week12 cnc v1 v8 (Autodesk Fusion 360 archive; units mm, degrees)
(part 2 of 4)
sketch "Sketch36" plane through (0, 0, 0) normal (0, -1, 0) x axis (1, 0, 0)
  line L1 (349.4349, 118.306) -> (345.9921, 118.306)
  line L2 (353.7135, 82.5845) -> (353.7135, 114.0274)
  line L3 (345.9921, 78.306) -> (349.4349, 78.306)
  line L4 (341.7135, 114.0274) -> (341.7135, 82.5845)
  line L5 (90.3858, 86.9447) -> (100.955, 105.2358)
  line L6 (90.3833, 79.9447) -> (90.3858, 86.9447)
  line L7 (115.751, 79.9356) -> (90.3833, 79.9447)
  line L8 (38.1164, 32.4224) -> (38.0988, 32.4224)
  line L9 (50.6125, 54.0752) -> (38.1164, 32.4224)
  line L10 (50.6113, 61.0752) -> (50.6125, 54.0752)
  line L11 (25.2538, 61.0708) -> (50.6113, 61.0752)
  line L12 (12, 96.0313) -> (12, 127.4742)
  line L13 (0, 91.7528) -> (7.7214, 91.7528)
  line L14 (0, 70.5018) -> (0, 91.7528)
  line L15 (175.6314, 0) -> (70.5018, 0)
  line L16 (452.7135, 50) -> (242.7135, 50)
  line L17 (624.9251, 0) -> (519.7955, 0)
  line L18 (695.4269, 91.7528) -> (695.4269, 70.5018)
  line L19 (687.7056, 91.7528) -> (695.4269, 91.7528)
  line L20 (683.427, 127.4742) -> (683.427, 96.0313)
  line L21 (695.4269, 131.7528) -> (687.7056, 131.7528)
  line L22 (695.4269, 136.7251) -> (695.4269, 131.7528)
  line L23 (695.5, 153.0037) -> (695.5, 141.0744)
  line L24 (655.5, 153.0037) -> (695.5, 153.0037)
  line L25 (655.5, 145.2822) -> (655.5, 153.0037)
  line L26 (606.1357, 141.0037) -> (651.2214, 141.0037)
  line L27 (601.8571, 153.0037) -> (601.8571, 145.2822)
  line L28 (561.8571, 153.0037) -> (601.8571, 153.0037)
  line L29 (561.8571, 145.2822) -> (561.8571, 153.0037)
  line L30 (512.4928, 141.0037) -> (557.5786, 141.0037)
  line L31 (508.2143, 153.0037) -> (508.2143, 145.2822)
  line L32 (468.2143, 153.0037) -> (508.2143, 153.0037)
  line L33 (468.2143, 145.2822) -> (468.2143, 153.0037)
  line L34 (418.85, 141.0037) -> (463.9357, 141.0037)
  line L35 (414.5714, 153.0037) -> (414.5714, 145.2822)
  line L36 (374.5714, 153.0037) -> (414.5714, 153.0037)
  line L37 (374.5714, 145.2822) -> (374.5714, 153.0037)
  line L38 (325.2071, 141.0037) -> (370.2929, 141.0037)
  line L39 (320.9286, 153.0037) -> (320.9286, 145.2822)
  line L40 (280.9286, 153.0037) -> (320.9286, 153.0037)
  line L41 (280.9286, 145.2822) -> (280.9286, 153.0037)
  line L42 (231.5643, 141.0037) -> (276.65, 141.0037)
  line L43 (227.2857, 153.0037) -> (227.2857, 145.2822)
  line L44 (187.2857, 153.0037) -> (227.2857, 153.0037)
  line L45 (187.2857, 145.2822) -> (187.2857, 153.0037)
  line L46 (137.9214, 141.0037) -> (183.0072, 141.0037)
  line L47 (133.6429, 153.0037) -> (133.6429, 145.2822)
  line L48 (93.6429, 153.0037) -> (133.6429, 153.0037)
  line L49 (93.6429, 145.2822) -> (93.6429, 153.0037)
  line L50 (44.2786, 141.0037) -> (89.3643, 141.0037)
  line L51 (40, 153.0037) -> (40, 145.2822)
  line L52 (0, 153.0037) -> (40, 153.0037)
  line L53 (0, 131.7528) -> (0, 153.0037)
  line L54 (7.7214, 131.7528) -> (0, 131.7528)
  line L55 (657.3164, 32.4124) -> (644.8145, 54.0752)
  line L56 (605.0437, 79.9447) -> (579.6759, 79.9356)
  line L57 (605.0412, 86.9447) -> (605.0437, 79.9447)
  line L58 (594.472, 105.2359) -> (605.0412, 86.9447)
  line L59 (644.8157, 61.0752) -> (670.1731, 61.0708)
  line L60 (644.8145, 54.0752) -> (644.8157, 61.0752)
  line L61 (38.1015, 32.3966) -> (38.1164, 32.4224)
  line L62 (38.0673, 32.4337) -> (38.1015, 32.3966)
  line L63 (38.0897, 32.4337) -> (38.0673, 32.4337)
  line L64 (38.1164, 32.4224) -> (38.0897, 32.4337)
  arc A1 centre (343.8528, 116.1667) radius 3.0254 clockwise from (341.7135, 114.0274) to (345.9921, 118.306)
  arc A2 centre (351.5742, 116.1667) radius 3.0254 clockwise from (349.4349, 118.306) to (353.7135, 114.0274)
  arc A3 centre (351.5742, 80.4453) radius 3.0254 clockwise from (353.7135, 82.5845) to (349.4349, 78.306)
  arc A4 centre (343.8528, 80.4453) radius 3.0254 clockwise from (345.9921, 78.306) to (341.7135, 82.5845)
  arc A5 centre (23.3262, 63.4026) radius 3.0254 clockwise from (25.2538, 61.0708) to (20.7983, 65.0647)
  arc A6 centre (70.5018, 70.5018) radius 50 clockwise from (20.7983, 65.0647) to (99.6962, 111.0936)
  arc A7 centre (99.9124, 108.0759) radius 3.0254 clockwise from (99.6962, 111.0936) to (100.955, 105.2358)
  arc A8 centre (117.6767, 77.6022) radius 3.0254 clockwise from (115.751, 79.9356) to (120.2051, 75.9408)
  arc A9 centre (70.5018, 70.5018) radius 50 clockwise from (120.2051, 75.9408) to (38.0988, 32.4224)
  arc A10 centre (9.8607, 129.6135) radius 3.0254 clockwise from (7.7214, 131.7528) to (12, 127.4742)
  arc A11 centre (9.8607, 93.892) radius 3.0254 clockwise from (12, 96.0313) to (7.7214, 91.7528)
  arc A12 centre (70.5018, 70.5018) radius 70.5018 clockwise from (70.5018, 0) to (0, 70.5018)
  arc A13 centre (175.6314, 20) radius 20 clockwise from (194.7977, 14.2857) to (175.6314, 0)
  arc A14 centre (242.7135, 0) radius 50 clockwise from (194.7977, 14.2857) to (242.7135, 50)
  arc A15 centre (452.7135, 0) radius 50 clockwise from (452.7135, 50) to (500.6292, 14.2857)
  arc A16 centre (519.7955, 20) radius 20 clockwise from (519.7955, 0) to (500.6292, 14.2857)
  arc A17 centre (624.9251, 70.5018) radius 70.5018 clockwise from (695.4269, 70.5018) to (624.9251, 0)
  arc A18 centre (685.5663, 93.892) radius 3.0254 clockwise from (687.7056, 91.7528) to (683.427, 96.0313)
  arc A19 centre (685.5663, 129.6135) radius 3.0254 clockwise from (683.427, 127.4742) to (687.7056, 131.7528)
  arc A20 centre (697.5662, 138.8644) radius 3.0254 clockwise from (695.4269, 136.7251) to (695.5, 141.0744)
  arc A21 centre (653.3607, 143.143) radius 3.0254 clockwise from (655.5, 145.2822) to (651.2214, 141.0037)
  arc A22 centre (603.9964, 143.143) radius 3.0254 clockwise from (606.1357, 141.0037) to (601.8571, 145.2822)
  arc A23 centre (559.7179, 143.143) radius 3.0254 clockwise from (561.8571, 145.2822) to (557.5786, 141.0037)
  arc A24 centre (510.3536, 143.143) radius 3.0254 clockwise from (512.4928, 141.0037) to (508.2143, 145.2822)
  arc A25 centre (466.075, 143.143) radius 3.0254 clockwise from (468.2143, 145.2822) to (463.9357, 141.0037)
  arc A26 centre (416.7107, 143.143) radius 3.0254 clockwise from (418.85, 141.0037) to (414.5714, 145.2822)
  arc A27 centre (372.4321, 143.143) radius 3.0254 clockwise from (374.5714, 145.2822) to (370.2929, 141.0037)
  arc A28 centre (323.0679, 143.143) radius 3.0254 clockwise from (325.2071, 141.0037) to (320.9286, 145.2822)
  arc A29 centre (278.7893, 143.143) radius 3.0254 clockwise from (280.9286, 145.2822) to (276.65, 141.0037)
  arc A30 centre (229.425, 143.143) radius 3.0254 clockwise from (231.5643, 141.0037) to (227.2857, 145.2822)
  arc A31 centre (185.1464, 143.143) radius 3.0254 clockwise from (187.2857, 145.2822) to (183.0072, 141.0037)
  arc A32 centre (135.7821, 143.143) radius 3.0254 clockwise from (137.9214, 141.0037) to (133.6429, 145.2822)
  arc A33 centre (91.5036, 143.143) radius 3.0254 clockwise from (93.6429, 145.2822) to (89.3643, 141.0037)
  arc A34 centre (42.1393, 143.143) radius 3.0254 clockwise from (44.2786, 141.0037) to (40, 145.2822)
  arc A35 centre (624.9251, 70.5018) radius 50 clockwise from (657.3164, 32.4124) to (575.2218, 75.9408)
  arc A36 centre (577.7502, 77.6022) radius 3.0254 clockwise from (575.2218, 75.9408) to (579.6759, 79.9356)
  arc A37 centre (595.5146, 108.0759) radius 3.0254 clockwise from (594.472, 105.2359) to (595.7308, 111.0936)
  arc A38 centre (624.9251, 70.5018) radius 50 clockwise from (595.7308, 111.0936) to (674.6286, 65.0647)
  arc A39 centre (672.1007, 63.4026) radius 3.0254 clockwise from (674.6286, 65.0647) to (670.1731, 61.0708)
  point P136 (38.1164, 32.4224)
  point P137 (38.1164, 32.4224)
  point P141 (38.1164, 32.4224)
  coincident P136 P137
  parallel L9 L61
  horizontal L63
  coincident P136 P141
extrude "Extrude5" add sketch "Sketch36" profile of A9 L8 L61 L62 L63 L64 to an object
base_feature "Base Feature31" bodies "Dogbones1 (3)"
combine "Combine1"
base_feature "Base Feature32" bodies "Dogbones1 (4)"
combine "Combine1"
base_feature "Base Feature33" bodies "Dogbones (18)"
combine "Combine2"
base_feature "Base Feature34" bodies "Dogbones1 (5)"
combine "Combine7"
extrude "Extrude2" cut of existing geometry blind -1
extrude "Extrude3" cut of existing geometry blind -3
extrude "Extrude4" cut of existing geometry blind -2
extrude "Extrude5" cut of existing geometry blind -2.5
extrude "Extrude1" cut of existing geometry blind -2
extrude "Extrude2" cut of existing geometry blind -2
extrude "Extrude6" cut of existing geometry blind -2
extrude "Extrude7" cut of existing geometry blind -2
extrude "Extrude8" cut of existing geometry blind -2
extrude "Extrude9" cut of existing geometry blind -2
extrude "Extrude3" cut of existing geometry blind -2
extrude "Extrude4" cut of existing geometry blind -2
extrude "Extrude5" cut of existing geometry blind -2
extrude "Extrude6" cut of existing geometry blind -2
extrude "Extrude7" cut of existing geometry blind -2
extrude "Extrude8" cut of existing geometry blind -2
sketch "Sketch37" plane through (0, 0, 12) normal (0, 0, 1) x axis (-1, 0, 0)
  line L1 (-1675.9921, -108.306) -> (-1679.4349, -108.306)
  line L2 (-1671.7135, -144.0275) -> (-1671.7135, -112.5846)
  line L3 (-1679.4349, -148.306) -> (-1675.9921, -148.306)
  line L4 (-1683.7135, -112.5846) -> (-1683.7135, -144.0275)
  line L5 (-1420.3858, -116.9448) -> (-1430.955, -135.2359)
  line L6 (-1420.3833, -109.9448) -> (-1420.3858, -116.9448)
  line L7 (-1445.751, -109.9357) -> (-1420.3833, -109.9448)
  line L8 (-1368.1164, -62.4225) -> (-1368.0988, -62.4225)
  line L9 (-1380.6125, -84.0753) -> (-1370.7136, -66.9229)
  line L10 (-1380.6113, -91.0753) -> (-1380.6125, -84.0753)
  line L11 (-1355.2538, -91.0708) -> (-1380.6113, -91.0753)
  line L12 (-1935.0437, -109.9448) -> (-1909.6759, -109.9357)
  line L13 (-1935.0412, -116.9448) -> (-1935.0437, -109.9448)
  line L14 (-1922.5334, -138.5909) -> (-1935.0412, -116.9448)
  line L15 (-1907.7027, -116.9349) -> (-1907.7028, -116.9349)
  line L16 (-1974.8157, -91.0753) -> (-2000.1731, -91.0708)
  line L17 (-1974.8145, -84.0753) -> (-1974.8157, -91.0753)
  line L18 (-1987.3106, -62.4225) -> (-1974.8145, -84.0753)
  line L19 (-1987.3281, -62.4225) -> (-1987.3106, -62.4225)
  line L20 (-1330, -121.7528) -> (-1337.7214, -121.7528)
  line L21 (-1330, -100.5019) -> (-1330, -121.7528)
  line L22 (-1505.6314, -30.0001) -> (-1400.5018, -30.0001)
  line L23 (-1782.7135, -80.0001) -> (-1572.7135, -80.0001)
  line L24 (-1954.9251, -30.0001) -> (-1849.7955, -30.0001)
  line L25 (-2025.4269, -121.7528) -> (-2025.4269, -100.5019)
  line L26 (-2017.7056, -121.7528) -> (-2025.4269, -121.7528)
  line L27 (-2013.427, -157.4743) -> (-2013.427, -126.0314)
  line L28 (-2025.4269, -161.7528) -> (-2017.7056, -161.7528)
  line L29 (-2025.4269, -171.0037) -> (-2025.4269, -161.7528)
  line L30 (-2025.5, -171.0037) -> (-2025.4269, -171.0037)
  line L31 (-2025.5, -183.0037) -> (-2025.5, -171.0037)
  line L32 (-1985.5, -183.0037) -> (-2025.5, -183.0037)
  line L33 (-1985.5, -175.2823) -> (-1985.5, -183.0037)
  line L34 (-1936.1357, -171.0037) -> (-1981.2214, -171.0037)
  line L35 (-1931.8571, -183.0037) -> (-1931.8571, -175.2823)
  line L36 (-1891.8571, -183.0037) -> (-1931.8571, -183.0037)
  line L37 (-1891.8571, -175.2823) -> (-1891.8571, -183.0037)
  line L38 (-1842.4928, -171.0037) -> (-1887.5786, -171.0037)
  line L39 (-1838.2143, -183.0037) -> (-1838.2143, -175.2823)
  line L40 (-1798.2143, -183.0037) -> (-1838.2143, -183.0037)
  line L41 (-1798.2143, -175.2823) -> (-1798.2143, -183.0037)
  line L42 (-1748.85, -171.0037) -> (-1793.9357, -171.0037)
  line L43 (-1744.5714, -183.0037) -> (-1744.5714, -175.2823)
  line L44 (-1704.5714, -183.0037) -> (-1744.5714, -183.0037)
  line L45 (-1704.5714, -175.2823) -> (-1704.5714, -183.0037)
  line L46 (-1655.2071, -171.0037) -> (-1700.2929, -171.0037)
  line L47 (-1650.9286, -183.0037) -> (-1650.9286, -175.2823)
  line L48 (-1610.9286, -183.0037) -> (-1650.9286, -183.0037)
  line L49 (-1610.9286, -175.2823) -> (-1610.9286, -183.0037)
  line L50 (-1561.5643, -171.0037) -> (-1606.65, -171.0037)
  line L51 (-1557.2857, -183.0037) -> (-1557.2857, -175.2823)
  line L52 (-1517.2857, -183.0037) -> (-1557.2857, -183.0037)
  line L53 (-1517.2857, -175.2823) -> (-1517.2857, -183.0037)
  line L54 (-1467.9214, -171.0037) -> (-1513.0072, -171.0037)
  line L55 (-1463.6429, -183.0037) -> (-1463.6429, -175.2823)
  line L56 (-1423.6429, -183.0037) -> (-1463.6429, -183.0037)
  line L57 (-1423.6429, -175.2823) -> (-1423.6429, -183.0037)
  line L58 (-1374.2786, -171.0037) -> (-1419.3643, -171.0037)
  line L59 (-1370, -183.0037) -> (-1370, -175.2823)
  line L60 (-1330, -183.0037) -> (-1370, -183.0037)
  line L61 (-1330, -161.7528) -> (-1330, -183.0037)
  line L62 (-1337.7214, -161.7528) -> (-1330, -161.7528)
  line L63 (-1342, -126.0314) -> (-1342, -157.4743)
  line L64 (-1922.5334, -138.5909) -> (-1935.0412, -116.9448)
  line L65 (-1906.94, -143.0545) -> (-1922.5334, -138.5909)
  line L66 (-1903.6641, -113.9992) -> (-1906.94, -143.0545)
  line L67 (-1912.281, -115.4947) -> (-1903.6641, -113.9992)
  line L68 (-1922.5334, -138.5909) -> (-1912.281, -115.4947)
  arc A1 centre (-1681.5742, -110.4453) radius 3.0254 clockwise from (-1683.7135, -112.5846) to (-1679.4349, -108.306)
  arc A2 centre (-1673.8528, -110.4453) radius 3.0254 clockwise from (-1675.9921, -108.306) to (-1671.7135, -112.5846)
  arc A3 centre (-1673.8528, -146.1668) radius 3.0254 clockwise from (-1671.7135, -144.0275) to (-1675.9921, -148.306)
  arc A4 centre (-1681.5742, -146.1668) radius 3.0254 clockwise from (-1679.4349, -148.306) to (-1683.7135, -144.0275)
  arc A5 centre (-1353.3262, -93.4026) radius 3.0254 clockwise from (-1355.2538, -91.0708) to (-1350.7983, -95.0648)
  arc A6 centre (-1400.5018, -100.5019) radius 50 clockwise from (-1350.7983, -95.0648) to (-1429.6962, -141.0936)
  arc A7 centre (-1429.9124, -138.076) radius 3.0254 clockwise from (-1429.6962, -141.0936) to (-1430.955, -135.2359)
  arc A8 centre (-1447.6767, -107.6023) radius 3.0254 clockwise from (-1445.751, -109.9357) to (-1450.2051, -105.9409)
  arc A9 centre (-1400.5018, -100.5019) radius 50 clockwise from (-1450.2051, -105.9409) to (-1369.7384, -61.0861)
  arc A10 centre (-1370.7142, -63.9229) radius 3 clockwise from (-1369.7384, -61.0861) to (-1368.1337, -62.3928)
  arc A11 centre (-1400.5018, -100.5019) radius 50 clockwise from (-1368.1337, -62.3928) to (-1368.0988, -62.4225)
  arc A12 centre (-1370.7142, -63.9229) radius 3 clockwise from (-1368.1164, -62.4225) to (-1370.7136, -66.9229)
  arc A13 centre (-1907.7502, -107.6023) radius 3.0254 clockwise from (-1905.2218, -105.9409) to (-1909.6759, -109.9357)
  arc A14 centre (-1954.9252, -100.5019) radius 50 clockwise from (-1907.7028, -116.9349) to (-1922.5334, -138.5909)
  arc A15 centre (-1954.9251, -100.5019) radius 50 clockwise from (-1907.7027, -116.9349) to (-2004.6286, -95.0648)
  arc A16 centre (-2002.1007, -93.4026) radius 3.0254 clockwise from (-2004.6286, -95.0648) to (-2000.1731, -91.0708)
  arc A17 centre (-1954.9251, -100.5019) radius 50 clockwise from (-1987.3281, -62.4225) to (-1905.2218, -105.9409)
  arc A18 centre (-1339.8607, -123.8921) radius 3.0254 clockwise from (-1342, -126.0314) to (-1337.7214, -121.7528)
  arc A19 centre (-1400.5018, -100.5019) radius 70.5018 clockwise from (-1400.5018, -30.0001) to (-1330, -100.5019)
  arc A20 centre (-1505.6314, -50.0001) radius 20 clockwise from (-1524.7977, -44.2858) to (-1505.6314, -30.0001)
  arc A21 centre (-1572.7135, -30.0001) radius 50 clockwise from (-1524.7977, -44.2858) to (-1572.7135, -80.0001)
  arc A22 centre (-1782.7135, -30.0001) radius 50 clockwise from (-1782.7135, -80.0001) to (-1830.6292, -44.2858)
  arc A23 centre (-1849.7955, -50.0001) radius 20 clockwise from (-1849.7955, -30.0001) to (-1830.6292, -44.2858)
  arc A24 centre (-1954.9251, -100.5019) radius 70.5018 clockwise from (-2025.4269, -100.5019) to (-1954.9251, -30.0001)
  arc A25 centre (-2015.5663, -123.8921) radius 3.0254 clockwise from (-2017.7056, -121.7528) to (-2013.427, -126.0314)
  arc A26 centre (-2015.5663, -159.6135) radius 3.0254 clockwise from (-2013.427, -157.4743) to (-2017.7056, -161.7528)
  arc A27 centre (-1983.3607, -173.143) radius 3.0254 clockwise from (-1985.5, -175.2823) to (-1981.2214, -171.0037)
  arc A28 centre (-1933.9964, -173.143) radius 3.0254 clockwise from (-1936.1357, -171.0037) to (-1931.8571, -175.2823)
  arc A29 centre (-1889.7179, -173.143) radius 3.0254 clockwise from (-1891.8571, -175.2823) to (-1887.5786, -171.0037)
  arc A30 centre (-1840.3536, -173.143) radius 3.0254 clockwise from (-1842.4928, -171.0037) to (-1838.2143, -175.2823)
  arc A31 centre (-1796.075, -173.143) radius 3.0254 clockwise from (-1798.2143, -175.2823) to (-1793.9357, -171.0037)
  arc A32 centre (-1746.7107, -173.143) radius 3.0254 clockwise from (-1748.85, -171.0037) to (-1744.5714, -175.2823)
  arc A33 centre (-1702.4321, -173.143) radius 3.0254 clockwise from (-1704.5714, -175.2823) to (-1700.2929, -171.0037)
  arc A34 centre (-1653.0679, -173.143) radius 3.0254 clockwise from (-1655.2071, -171.0037) to (-1650.9286, -175.2823)
  arc A35 centre (-1608.7893, -173.143) radius 3.0254 clockwise from (-1610.9286, -175.2823) to (-1606.65, -171.0037)
  arc A36 centre (-1559.425, -173.143) radius 3.0254 clockwise from (-1561.5643, -171.0037) to (-1557.2857, -175.2823)
  arc A37 centre (-1515.1464, -173.143) radius 3.0254 clockwise from (-1517.2857, -175.2823) to (-1513.0072, -171.0037)
  arc A38 centre (-1465.7821, -173.143) radius 3.0254 clockwise from (-1467.9214, -171.0037) to (-1463.6429, -175.2823)
  arc A39 centre (-1421.5036, -173.143) radius 3.0254 clockwise from (-1423.6429, -175.2823) to (-1419.3643, -171.0037)
  arc A40 centre (-1372.1393, -173.143) radius 3.0254 clockwise from (-1374.2786, -171.0037) to (-1370, -175.2823)
  arc A41 centre (-1339.8607, -159.6135) radius 3.0254 clockwise from (-1337.7214, -161.7528) to (-1342, -157.4743)
  point P142 (-1922.5334, -138.5909)
  point P143 (-1922.5334, -138.5909)
  point P147 (-1922.5334, -138.5909)
  coincident P142 P143
  coincident P142 P147
extrude "Extrude1" add sketch "Sketch37" profile of A14 L15 A15 L65 to an object
base_feature "Base Feature35" bodies "Dogbones1 (6)"
combine "Combine7"
sketch "Sketch38" plane through (0, 0, 12) normal (0, 0, 1) x axis (-1, 0, 0)
  line L1 (-1935.0437, -109.9448) -> (-1909.6759, -109.9357)
  line L2 (-1935.0412, -116.9448) -> (-1935.0437, -109.9448)
  line L3 (-1922.5334, -138.5909) -> (-1935.0412, -116.9448)
  line L4 (-1922.5333, -138.5909) -> (-1922.5334, -138.5909)
  line L5 (-1974.8157, -91.0753) -> (-2000.1731, -91.0708)
  line L6 (-1974.8145, -84.0753) -> (-1974.8157, -91.0753)
  line L7 (-1987.3106, -62.4225) -> (-1974.8145, -84.0753)
  line L8 (-1987.3281, -62.4225) -> (-1987.3106, -62.4225)
  line L9 (-1420.3858, -116.9448) -> (-1430.955, -135.2359)
  line L10 (-1420.3833, -109.9448) -> (-1420.3858, -116.9448)
  line L11 (-1445.751, -109.9357) -> (-1420.3833, -109.9448)
  line L12 (-1368.1164, -62.4225) -> (-1368.0988, -62.4225)
  line L13 (-1380.6125, -84.0753) -> (-1370.7136, -66.9229)
  line L14 (-1380.6113, -91.0753) -> (-1380.6125, -84.0753)
  line L15 (-1355.2538, -91.0708) -> (-1380.6113, -91.0753)
  line L16 (-1675.9921, -108.306) -> (-1679.4349, -108.306)
  line L17 (-1671.7135, -144.0275) -> (-1671.7135, -112.5846)
  line L18 (-1679.4349, -148.306) -> (-1675.9921, -148.306)
  line L19 (-1683.7135, -112.5846) -> (-1683.7135, -144.0275)
  line L20 (-2025.5, -183.0037) -> (-2025.5, -171.0744)
  line L21 (-1985.5, -183.0037) -> (-2025.5, -183.0037)
  line L22 (-1985.5, -175.2823) -> (-1985.5, -183.0037)
  line L23 (-1936.1357, -171.0037) -> (-1981.2214, -171.0037)
  line L24 (-1931.8571, -183.0037) -> (-1931.8571, -175.2823)
  line L25 (-1891.8571, -183.0037) -> (-1931.8571, -183.0037)
  line L26 (-1891.8571, -175.2823) -> (-1891.8571, -183.0037)
  line L27 (-1842.4928, -171.0037) -> (-1887.5786, -171.0037)
  line L28 (-1838.2143, -183.0037) -> (-1838.2143, -175.2823)
  line L29 (-1798.2143, -183.0037) -> (-1838.2143, -183.0037)
  line L30 (-1798.2143, -175.2823) -> (-1798.2143, -183.0037)
  line L31 (-1748.85, -171.0037) -> (-1793.9357, -171.0037)
  line L32 (-1744.5714, -183.0037) -> (-1744.5714, -175.2823)
  line L33 (-1704.5714, -183.0037) -> (-1744.5714, -183.0037)
  line L34 (-1704.5714, -175.2823) -> (-1704.5714, -183.0037)
  line L35 (-1655.2071, -171.0037) -> (-1700.2929, -171.0037)
  line L36 (-1650.9286, -183.0037) -> (-1650.9286, -175.2823)
  line L37 (-1610.9286, -183.0037) -> (-1650.9286, -183.0037)
  line L38 (-1610.9286, -175.2823) -> (-1610.9286, -183.0037)
  line L39 (-1561.5643, -171.0037) -> (-1606.65, -171.0037)
  line L40 (-1557.2857, -183.0037) -> (-1557.2857, -175.2823)
  line L41 (-1517.2857, -183.0037) -> (-1557.2857, -183.0037)
  line L42 (-1517.2857, -175.2823) -> (-1517.2857, -183.0037)
  line L43 (-1467.9214, -171.0037) -> (-1513.0072, -171.0037)
  line L44 (-1463.6429, -183.0037) -> (-1463.6429, -175.2823)
  line L45 (-1423.6429, -183.0037) -> (-1463.6429, -183.0037)
  line L46 (-1423.6429, -175.2823) -> (-1423.6429, -183.0037)
  line L47 (-1374.2786, -171.0037) -> (-1419.3643, -171.0037)
  line L48 (-1370, -183.0037) -> (-1370, -175.2823)
  line L49 (-1330, -183.0037) -> (-1370, -183.0037)
  line L50 (-1330, -161.7528) -> (-1330, -183.0037)
  line L51 (-1337.7214, -161.7528) -> (-1330, -161.7528)
  line L52 (-1342, -126.0314) -> (-1342, -157.4743)
  line L53 (-1330, -121.7528) -> (-1337.7214, -121.7528)
  line L54 (-1330, -100.5019) -> (-1330, -121.7528)
  line L55 (-1505.6314, -30.0001) -> (-1400.5018, -30.0001)
  line L56 (-1782.7135, -80.0001) -> (-1572.7135, -80.0001)
  line L57 (-1954.9251, -30.0001) -> (-1849.7955, -30.0001)
  line L58 (-2025.4269, -121.7528) -> (-2025.4269, -100.5019)
  line L59 (-2017.7056, -121.7528) -> (-2025.4269, -121.7528)
  line L60 (-2013.427, -157.4743) -> (-2013.427, -126.0314)
  line L61 (-2025.4269, -161.7528) -> (-2017.7056, -161.7528)
  line L62 (-2025.4269, -166.7252) -> (-2025.4269, -161.7528)
  line L63 (-1987.3281, -62.4225) -> (-1987.3106, -62.4225)
  line L64 (-1987.3227, -62.4017) -> (-1987.3106, -62.4225)
  line L65 (-1987.3382, -62.4335) -> (-1987.3227, -62.4017)
  line L66 (-1987.3287, -62.4382) -> (-1987.3382, -62.4335)
  line L67 (-1987.3106, -62.4225) -> (-1987.3287, -62.4382)
  arc A1 centre (-1907.7502, -107.6023) radius 3.0254 clockwise from (-1905.2218, -105.9409) to (-1909.6759, -109.9357)
  arc A2 centre (-1954.9251, -100.5019) radius 50 clockwise from (-1922.5333, -138.5909) to (-2004.6286, -95.0648)
  arc A3 centre (-2002.1007, -93.4026) radius 3.0254 clockwise from (-2004.6286, -95.0648) to (-2000.1731, -91.0708)
  arc A4 centre (-1954.9251, -100.5019) radius 50 clockwise from (-1987.3281, -62.4225) to (-1905.2218, -105.9409)
  arc A5 centre (-1353.3262, -93.4026) radius 3.0254 clockwise from (-1355.2538, -91.0708) to (-1350.7983, -95.0648)
  arc A6 centre (-1400.5018, -100.5019) radius 50 clockwise from (-1350.7983, -95.0648) to (-1429.6962, -141.0936)
  arc A7 centre (-1429.9124, -138.076) radius 3.0254 clockwise from (-1429.6962, -141.0936) to (-1430.955, -135.2359)
  arc A8 centre (-1447.6767, -107.6023) radius 3.0254 clockwise from (-1445.751, -109.9357) to (-1450.2051, -105.9409)
  arc A9 centre (-1400.5018, -100.5019) radius 50 clockwise from (-1450.2051, -105.9409) to (-1369.7384, -61.0861)
  arc A10 centre (-1370.7142, -63.9229) radius 3 clockwise from (-1369.7384, -61.0861) to (-1368.1337, -62.3928)
  arc A11 centre (-1400.5018, -100.5019) radius 50 clockwise from (-1368.1337, -62.3928) to (-1368.0988, -62.4225)
  arc A12 centre (-1370.7142, -63.9229) radius 3 clockwise from (-1368.1164, -62.4225) to (-1370.7136, -66.9229)
  arc A13 centre (-1681.5742, -110.4453) radius 3.0254 clockwise from (-1683.7135, -112.5846) to (-1679.4349, -108.306)
  arc A14 centre (-1673.8528, -110.4453) radius 3.0254 clockwise from (-1675.9921, -108.306) to (-1671.7135, -112.5846)
  arc A15 centre (-1673.8528, -146.1668) radius 3.0254 clockwise from (-1671.7135, -144.0275) to (-1675.9921, -148.306)
  arc A16 centre (-1681.5742, -146.1668) radius 3.0254 clockwise from (-1679.4349, -148.306) to (-1683.7135, -144.0275)
  arc A17 centre (-2027.5662, -168.8645) radius 3.0254 clockwise from (-2025.4269, -166.7252) to (-2025.5, -171.0744)
  arc A18 centre (-1983.3607, -173.143) radius 3.0254 clockwise from (-1985.5, -175.2823) to (-1981.2214, -171.0037)
  arc A19 centre (-1933.9964, -173.143) radius 3.0254 clockwise from (-1936.1357, -171.0037) to (-1931.8571, -175.2823)
  arc A20 centre (-1889.7179, -173.143) radius 3.0254 clockwise from (-1891.8571, -175.2823) to (-1887.5786, -171.0037)
  arc A21 centre (-1840.3536, -173.143) radius 3.0254 clockwise from (-1842.4928, -171.0037) to (-1838.2143, -175.2823)
  arc A22 centre (-1796.075, -173.143) radius 3.0254 clockwise from (-1798.2143, -175.2823) to (-1793.9357, -171.0037)
  arc A23 centre (-1746.7107, -173.143) radius 3.0254 clockwise from (-1748.85, -171.0037) to (-1744.5714, -175.2823)
  arc A24 centre (-1702.4321, -173.143) radius 3.0254 clockwise from (-1704.5714, -175.2823) to (-1700.2929, -171.0037)
  arc A25 centre (-1653.0679, -173.143) radius 3.0254 clockwise from (-1655.2071, -171.0037) to (-1650.9286, -175.2823)
  arc A26 centre (-1608.7893, -173.143) radius 3.0254 clockwise from (-1610.9286, -175.2823) to (-1606.65, -171.0037)
  arc A27 centre (-1559.425, -173.143) radius 3.0254 clockwise from (-1561.5643, -171.0037) to (-1557.2857, -175.2823)
  arc A28 centre (-1515.1464, -173.143) radius 3.0254 clockwise from (-1517.2857, -175.2823) to (-1513.0072, -171.0037)
  arc A29 centre (-1465.7821, -173.143) radius 3.0254 clockwise from (-1467.9214, -171.0037) to (-1463.6429, -175.2823)
  arc A30 centre (-1421.5036, -173.143) radius 3.0254 clockwise from (-1423.6429, -175.2823) to (-1419.3643, -171.0037)
  arc A31 centre (-1372.1393, -173.143) radius 3.0254 clockwise from (-1374.2786, -171.0037) to (-1370, -175.2823)
  arc A32 centre (-1339.8607, -159.6135) radius 3.0254 clockwise from (-1337.7214, -161.7528) to (-1342, -157.4743)
  arc A33 centre (-1339.8607, -123.8921) radius 3.0254 clockwise from (-1342, -126.0314) to (-1337.7214, -121.7528)
  arc A34 centre (-1400.5018, -100.5019) radius 70.5018 clockwise from (-1400.5018, -30.0001) to (-1330, -100.5019)
  arc A35 centre (-1505.6314, -50.0001) radius 20 clockwise from (-1524.7977, -44.2858) to (-1505.6314, -30.0001)
  arc A36 centre (-1572.7135, -30.0001) radius 50 clockwise from (-1524.7977, -44.2858) to (-1572.7135, -80.0001)
  arc A37 centre (-1782.7135, -30.0001) radius 50 clockwise from (-1782.7135, -80.0001) to (-1830.6292, -44.2858)
  arc A38 centre (-1849.7955, -50.0001) radius 20 clockwise from (-1849.7955, -30.0001) to (-1830.6292, -44.2858)
  arc A39 centre (-1954.9251, -100.5019) radius 70.5018 clockwise from (-2025.4269, -100.5019) to (-1954.9251, -30.0001)
  arc A40 centre (-2015.5663, -123.8921) radius 3.0254 clockwise from (-2017.7056, -121.7528) to (-2013.427, -126.0314)
  arc A41 centre (-2015.5663, -159.6135) radius 3.0254 clockwise from (-2013.427, -157.4743) to (-2017.7056, -161.7528)
  point P140 (-1987.3106, -62.4225)
  point P142 (-1987.3106, -62.4225)
  coincident P140 P142
  perpendicular L65 L66
  parallel L7 L64
extrude "Extrude2" add sketch "Sketch38" profile of L8 A4 L63 L64 L65 L66 L67 to an object
base_feature "Base Feature36" bodies "Dogbones (19)"
combine "Combine8"
sketch "Sketch40" plane through (0, 0, 0) normal (0, 0, -1) x axis (1, 0, 0)
  line L1 (1683.7135, -144.0275) -> (1683.7135, -112.5846)
  line L2 (1675.9921, -148.306) -> (1679.4349, -148.306)
  line L3 (1671.7135, -112.5846) -> (1671.7135, -144.0275)
  line L4 (1679.4349, -108.306) -> (1675.9921, -108.306)
  line L5 (1380.6113, -91.0753) -> (1355.2538, -91.0708)
  line L6 (1380.6125, -84.0753) -> (1380.6113, -91.0753)
  line L7 (1370.7136, -66.9229) -> (1380.6125, -84.0753)
  line L8 (1368.0988, -62.4225) -> (1368.1164, -62.4225)
  line L9 (1420.3833, -109.9448) -> (1445.751, -109.9357)
  line L10 (1420.3858, -116.9448) -> (1420.3833, -109.9448)
  line L11 (1430.955, -135.2359) -> (1420.3858, -116.9448)
  line L12 (2025.4269, -161.7528) -> (2025.4269, -166.7252)
  line L13 (2017.7056, -161.7528) -> (2025.4269, -161.7528)
  line L14 (2013.427, -126.0314) -> (2013.427, -157.4743)
  line L15 (2025.4269, -121.7528) -> (2017.7056, -121.7528)
  line L16 (2025.4269, -100.5019) -> (2025.4269, -121.7528)
  line L17 (1849.7955, -30.0001) -> (1954.9251, -30.0001)
  line L18 (1572.7135, -80.0001) -> (1782.7135, -80.0001)
  line L19 (1400.5018, -30.0001) -> (1505.6314, -30.0001)
  line L20 (1330, -121.7528) -> (1330, -100.5019)
  line L21 (1337.7214, -121.7528) -> (1330, -121.7528)
  line L22 (1342, -157.4743) -> (1342, -126.0314)
  line L23 (1330, -161.7528) -> (1337.7214, -161.7528)
  line L24 (1330, -183.0037) -> (1330, -161.7528)
  line L25 (1370, -183.0037) -> (1330, -183.0037)
  line L26 (1370, -175.2823) -> (1370, -183.0037)
  line L27 (1419.3643, -171.0037) -> (1374.2786, -171.0037)
  line L28 (1423.6429, -183.0037) -> (1423.6429, -175.2823)
  line L29 (1463.6429, -183.0037) -> (1423.6429, -183.0037)
  line L30 (1463.6429, -175.2823) -> (1463.6429, -183.0037)
  line L31 (1513.0072, -171.0037) -> (1467.9214, -171.0037)
  line L32 (1517.2857, -183.0037) -> (1517.2857, -175.2823)
  line L33 (1557.2857, -183.0037) -> (1517.2857, -183.0037)
  line L34 (1557.2857, -175.2823) -> (1557.2857, -183.0037)
  line L35 (1606.65, -171.0037) -> (1561.5643, -171.0037)
  line L36 (1610.9286, -183.0037) -> (1610.9286, -175.2823)
  line L37 (1650.9286, -183.0037) -> (1610.9286, -183.0037)
  line L38 (1650.9286, -175.2823) -> (1650.9286, -183.0037)
  line L39 (1700.2929, -171.0037) -> (1655.2071, -171.0037)
  line L40 (1704.5714, -183.0037) -> (1704.5714, -175.2823)
  line L41 (1744.5714, -183.0037) -> (1704.5714, -183.0037)
  line L42 (1744.5714, -175.2823) -> (1744.5714, -183.0037)
  line L43 (1793.9357, -171.0037) -> (1748.85, -171.0037)
  line L44 (1798.2143, -183.0037) -> (1798.2143, -175.2823)
  line L45 (1838.2143, -183.0037) -> (1798.2143, -183.0037)
  line L46 (1838.2143, -175.2823) -> (1838.2143, -183.0037)
  line L47 (1887.5786, -171.0037) -> (1842.4928, -171.0037)
  line L48 (1891.8571, -183.0037) -> (1891.8571, -175.2823)
  line L49 (1931.8571, -183.0037) -> (1891.8571, -183.0037)
  line L50 (1931.8571, -175.2823) -> (1931.8571, -183.0037)
  line L51 (1981.2214, -171.0037) -> (1936.1357, -171.0037)
  line L52 (1985.5, -183.0037) -> (1985.5, -175.2823)
  line L53 (2025.5, -183.0037) -> (1985.5, -183.0037)
  line L54 (2025.5, -171.0744) -> (2025.5, -183.0037)
  line L55 (1974.8145, -84.0753) -> (1985.3802, -65.7675)
  line L56 (1974.8157, -91.0753) -> (1974.8145, -84.0753)
  line L57 (2000.1731, -91.0708) -> (1974.8157, -91.0753)
  line L58 (1922.5334, -138.5909) -> (1922.5333, -138.5909)
  line L59 (1935.0412, -116.9448) -> (1922.5334, -138.5909)
  line L60 (1935.0437, -109.9448) -> (1935.0412, -116.9448)
  line L61 (1909.6759, -109.9357) -> (1935.0437, -109.9448)
  line L62 (1922.5438, -138.573) -> (1927.5325, -142.3307)
  line L63 (1922.5334, -138.5909) -> (1935.0412, -116.9448)
  line L64 (1918.2293, -139.1753) -> (1927.5325, -142.3307)
  line L65 (1922.5438, -138.573) -> (1918.2293, -139.1753)
  arc A1 centre (1681.5742, -110.4453) radius 3.0254 clockwise from (1679.4349, -108.306) to (1683.7135, -112.5846)
  arc A2 centre (1681.5742, -146.1668) radius 3.0254 clockwise from (1683.7135, -144.0275) to (1679.4349, -148.306)
  arc A3 centre (1673.8528, -146.1668) radius 3.0254 clockwise from (1675.9921, -148.306) to (1671.7135, -144.0275)
  arc A4 centre (1673.8528, -110.4453) radius 3.0254 clockwise from (1671.7135, -112.5846) to (1675.9921, -108.306)
  arc A5 centre (1353.3262, -93.4026) radius 3.0254 clockwise from (1350.7983, -95.0648) to (1355.2538, -91.0708)
  arc A6 centre (1370.7142, -63.9229) radius 3 clockwise from (1370.7136, -66.9229) to (1368.1164, -62.4225)
  arc A7 centre (1400.5018, -100.5019) radius 50 clockwise from (1368.0988, -62.4225) to (1368.1337, -62.3928)
  arc A8 centre (1370.7142, -63.9229) radius 3 clockwise from (1368.1337, -62.3928) to (1369.7384, -61.0861)
  arc A9 centre (1400.5018, -100.5019) radius 50 clockwise from (1369.7384, -61.0861) to (1450.2051, -105.9409)
  arc A10 centre (1447.6767, -107.6023) radius 3.0254 clockwise from (1450.2051, -105.9409) to (1445.751, -109.9357)
  arc A11 centre (1429.9124, -138.076) radius 3.0254 clockwise from (1430.955, -135.2359) to (1429.6962, -141.0936)
  arc A12 centre (1400.5018, -100.5019) radius 50 clockwise from (1429.6962, -141.0936) to (1350.7983, -95.0648)
  arc A13 centre (2027.5662, -168.8645) radius 3.0254 clockwise from (2025.5, -171.0744) to (2025.4269, -166.7252)
  arc A14 centre (2015.5663, -159.6135) radius 3.0254 clockwise from (2017.7056, -161.7528) to (2013.427, -157.4743)
  arc A15 centre (2015.5663, -123.8921) radius 3.0254 clockwise from (2013.427, -126.0314) to (2017.7056, -121.7528)
  arc A16 centre (1954.9251, -100.5019) radius 70.5018 clockwise from (1954.9251, -30.0001) to (2025.4269, -100.5019)
  arc A17 centre (1849.7955, -50.0001) radius 20 clockwise from (1830.6292, -44.2858) to (1849.7955, -30.0001)
  arc A18 centre (1782.7135, -30.0001) radius 50 clockwise from (1830.6292, -44.2858) to (1782.7135, -80.0001)
  arc A19 centre (1572.7135, -30.0001) radius 50 clockwise from (1572.7135, -80.0001) to (1524.7977, -44.2858)
  arc A20 centre (1505.6314, -50.0001) radius 20 clockwise from (1505.6314, -30.0001) to (1524.7977, -44.2858)
  arc A21 centre (1400.5018, -100.5019) radius 70.5018 clockwise from (1330, -100.5019) to (1400.5018, -30.0001)
  arc A22 centre (1339.8607, -123.8921) radius 3.0254 clockwise from (1337.7214, -121.7528) to (1342, -126.0314)
  arc A23 centre (1339.8607, -159.6135) radius 3.0254 clockwise from (1342, -157.4743) to (1337.7214, -161.7528)
  arc A24 centre (1372.1393, -173.143) radius 3.0254 clockwise from (1370, -175.2823) to (1374.2786, -171.0037)
  arc A25 centre (1421.5036, -173.143) radius 3.0254 clockwise from (1419.3643, -171.0037) to (1423.6429, -175.2823)
  arc A26 centre (1465.7821, -173.143) radius 3.0254 clockwise from (1463.6429, -175.2823) to (1467.9214, -171.0037)
  arc A27 centre (1515.1464, -173.143) radius 3.0254 clockwise from (1513.0072, -171.0037) to (1517.2857, -175.2823)
  arc A28 centre (1559.425, -173.143) radius 3.0254 clockwise from (1557.2857, -175.2823) to (1561.5643, -171.0037)
  arc A29 centre (1608.7893, -173.143) radius 3.0254 clockwise from (1606.65, -171.0037) to (1610.9286, -175.2823)
  arc A30 centre (1653.0679, -173.143) radius 3.0254 clockwise from (1650.9286, -175.2823) to (1655.2071, -171.0037)
  arc A31 centre (1702.4321, -173.143) radius 3.0254 clockwise from (1700.2929, -171.0037) to (1704.5714, -175.2823)
  arc A32 centre (1746.7107, -173.143) radius 3.0254 clockwise from (1744.5714, -175.2823) to (1748.85, -171.0037)
  arc A33 centre (1796.075, -173.143) radius 3.0254 clockwise from (1793.9357, -171.0037) to (1798.2143, -175.2823)
  arc A34 centre (1840.3536, -173.143) radius 3.0254 clockwise from (1838.2143, -175.2823) to (1842.4928, -171.0037)
  arc A35 centre (1889.7179, -173.143) radius 3.0254 clockwise from (1887.5786, -171.0037) to (1891.8571, -175.2823)
  arc A36 centre (1933.9964, -173.143) radius 3.0254 clockwise from (1931.8571, -175.2823) to (1936.1357, -171.0037)
  arc A37 centre (1983.3607, -173.143) radius 3.0254 clockwise from (1981.2214, -171.0037) to (1985.5, -175.2823)
  arc A38 centre (1984.3353, -62.9283) radius 3.0254 clockwise from (1984.12, -59.9106) to (1985.3802, -65.7675)
  arc A39 centre (2002.1007, -93.4026) radius 3.0254 clockwise from (2000.1731, -91.0708) to (2004.6286, -95.0648)
  arc A40 centre (1907.7502, -107.6023) radius 3.0254 clockwise from (1909.6759, -109.9357) to (1905.2218, -105.9409)
  arc A41 centre (1954.9251, -100.5019) radius 50 clockwise from (1905.2218, -105.9409) to (1984.12, -59.9106)
  arc A42 centre (1954.9251, -100.5019) radius 50 clockwise from (2004.6286, -95.0648) to (1922.5333, -138.5909)
  point P143 (1922.5438, -138.573)
  point P142 (1927.5325, -142.3307)
  coincident L59 P143
  coincident P142 A42
extrude "Extrude5" add sketch "Sketch40" profile of L58 L59 L62 L63 L64 L65 A42 to an object
base_feature "Base Feature37" bodies "Dogbones (20)"
combine "Combine9"
base_feature "Base Feature2"
base_feature "Base Feature1"
combine "Combine2"
external_derived "ExternalDerived1" bodies "wall1", "wall0", "wall2"
derived_instance "DerivedInstance1"
derived_instance "DerivedInstance2"
derived_instance "DerivedInstance3"
external_derived "ExternalDerived2" bodies "Body1 (1)"
fillet "Fillet1" radius 3
fillet "Fillet1" radius 3
fillet "Fillet2" radius 3
fillet "Fillet3" radius 3
fillet "Fillet1" radius 3
fillet "Fillet2" radius 3
copy_paste_bodies "CopyPasteBodies1"
move "Move1"
copy_paste_bodies "CopyPasteBodies2"
move "Move2"
component_from_bodies "Body->Comp4"
component_from_bodies "Body->Comp5"
component_from_bodies "Body->Comp6"
copy_paste "CopyPaste1"
sketch "Sketch1" plane through (-3007.1784, -743.0667, 0) normal (1, 0, 0) x axis (0, 1, 0)
  line L1 (614, 255) -> (614, 273)
  line L2 (621.7214, 252) -> (617, 252)
  line L3 (626, 228) -> (626, 247.7214)
  line L4 (729.5, 228) -> (626, 228)
  line L5 (626, 84) -> (729.5, 84)
  line L6 (626, 64.2786) -> (626, 84)
  line L7 (617, 60) -> (621.7214, 60)
  line L8 (614, 39) -> (614, 57)
  line L9 (621.7214, 36) -> (617, 36)
  line L10 (626, 12) -> (626, 31.7214)
  line L11 (896, 12) -> (626, 12)
  line L12 (896, 101.7214) -> (896, 12)
  line L13 (905, 106) -> (900.2786, 106)
  line L14 (908, 203) -> (908, 109)
  line L15 (900.2786, 206) -> (905, 206)
  line L16 (896, 300) -> (896, 210.2786)
  line L17 (685.4, 300) -> (896, 300)
  line L18 (685.4, 292.2786) -> (685.4, 300)
  line L19 (660.8786, 288) -> (681.1214, 288)
  line L20 (656.6, 300) -> (656.6, 292.2786)
  line L21 (626, 300) -> (656.6, 300)
  line L22 (626, 280.2786) -> (626, 300)
  line L23 (617, 276) -> (621.7214, 276)
  arc A1 centre (617, 273) radius 3 clockwise from (614, 273) to (617, 276)
  arc A2 centre (617, 255) radius 3 clockwise from (617, 252) to (614, 255)
  arc A3 centre (623.8607, 249.8607) radius 3.0254 clockwise from (621.7214, 252) to (626, 247.7214)
  arc A4 centre (729.5, 156) radius 72 clockwise from (729.5, 228) to (729.5, 84)
  arc A5 centre (623.8607, 62.1393) radius 3.0254 clockwise from (626, 64.2786) to (621.7214, 60)
  arc A6 centre (617, 57) radius 3 clockwise from (614, 57) to (617, 60)
  arc A7 centre (617, 39) radius 3 clockwise from (617, 36) to (614, 39)
  arc A8 centre (623.8607, 33.8607) radius 3.0254 clockwise from (621.7214, 36) to (626, 31.7214)
  arc A9 centre (898.1393, 103.8607) radius 3.0254 clockwise from (896, 101.7214) to (900.2786, 106)
  arc A10 centre (905, 109) radius 3 clockwise from (908, 109) to (905, 106)
  arc A11 centre (905, 203) radius 3 clockwise from (905, 206) to (908, 203)
  arc A12 centre (898.1393, 208.1393) radius 3.0254 clockwise from (900.2786, 206) to (896, 210.2786)
  arc A13 centre (683.2607, 290.1393) radius 3.0254 clockwise from (685.4, 292.2786) to (681.1214, 288)
  arc A14 centre (658.7393, 290.1393) radius 3.0254 clockwise from (660.8786, 288) to (656.6, 292.2786)
  arc A15 centre (623.8607, 278.1393) radius 3.0254 clockwise from (626, 280.2786) to (621.7214, 276)
step "Arrange1" AngleFromX 0 Priority 500 AngleFromX 0 Priority 500 AngleFromX 0 Priority 500 AngleFromX 0 Priority 500 AngleFromX 0 Priority 500 AngleFromX 0 Priority 500 AngleFromX 0 Priority 500 originOffsetX 1000 originOffsetY 1000 envelopeLength 914.4 (= "3 ft") envelopeWidth 1219.2 (= "4 ft") envelopeSpacing 0 grainDirection 0 objectSpacing 20 frameWidth 20 placementClearance 30
step "Arrange11" AngleFromX 0 Priority 500 AngleFromX 0 Priority 500 AngleFromX 0 Priority 500 AngleFromX 0 Priority 500 AngleFromX 0 Priority 500 AngleFromX 0 Priority 500 AngleFromX 0 Priority 500 AngleFromX 0 Priority 500 AngleFromX 0 Priority 500 AngleFromX 0 Priority 500 AngleFromX 0 Priority 500 AngleFromX 0 Priority 500 AngleFromX 0 Priority 500 originOffsetX 1000 originOffsetY 1500 envelopeLength 2438 envelopeWidth 1219 envelopeSpacing 0 grainDirection 0 objectSpacing 29 frameWidth 25 placementClearance 20 AngleFromX 0 Priority 500 AngleFromX 0 Priority 500
sketch "Sketch41" plane through (0, 0.0001, -20) normal (0, 0, 1) x axis (-1, 0, 0)
  line L1 (-1504, -2368.0072) -> (-1504, -2380.7268)
  line L2 (-1926, -2368.0072) -> (-1504, -2368.0072)
  line L3 (-1926, -2380.7268) -> (-1926, -2368.0072)
  line L4 (-1926, -2480.0054) -> (-1926, -2385.0054)
  line L5 (-1926, -2653.0072) -> (-1926, -2484.2839)
  line L6 (-1853.372, -2668.0072) -> (-1911, -2668.0072)
  line L7 (-1519, -2668.0072) -> (-1576.9045, -2668.0072)
  line L8 (-1504, -2484.2839) -> (-1504, -2653.0072)
  line L9 (-1504, -2385.0054) -> (-1504, -2480.0054)
  line L10 (-2935.833, -1472.2698) -> (-497.833, -1472.2698)
  line L11 (-2935.833, -2691.2698) -> (-2935.833, -1472.2698)
  line L12 (-497.833, -2691.2698) -> (-2935.833, -2691.2698)
  line L13 (-497.833, -1472.2698) -> (-497.833, -2691.2698)
  arc A1 centre (-1501.8607, -2382.8661) radius 3.0254 clockwise from (-1504, -2385.0054) to (-1504, -2380.7268)
  arc A2 centre (-1928.1393, -2382.8661) radius 3.0254 clockwise from (-1926, -2380.7268) to (-1926, -2385.0054)
  arc A3 centre (-1928.1393, -2482.1447) radius 3.0254 clockwise from (-1926, -2480.0054) to (-1926, -2484.2839)
  arc A4 centre (-1911, -2653.0072) radius 15 clockwise from (-1911, -2668.0072) to (-1926, -2653.0072)
  arc A5 centre (-1853.372, -2653.0072) radius 15 clockwise from (-1838.6232, -2655.7409) to (-1853.372, -2668.0072)
  arc A6 centre (-1715.1382, -2678.6289) radius 125.5882 clockwise from (-1838.6232, -2655.7409) to (-1591.6533, -2655.7409)
  arc A7 centre (-1576.9045, -2653.0072) radius 15 clockwise from (-1576.9045, -2668.0072) to (-1591.6533, -2655.7409)
  arc A8 centre (-1519, -2653.0072) radius 15 clockwise from (-1504, -2653.0072) to (-1519, -2668.0072)
  arc A9 centre (-1501.8607, -2482.1447) radius 3.0254 clockwise from (-1504, -2484.2839) to (-1504, -2480.0054)
  point P29 (-497.833, -1472.2698)
  point P32 (-497.833, -2691.2698)
  point P31 (-2935.833, -2691.2698)
  horizontal L10
  vertical L11
  horizontal L12
  vertical L13
  dimension "d622" distance P29 P32 = 1219
  dimension "d623" distance P31 P32 = 2438
step "Arrange8" AngleFromX 0 Priority 500 AngleFromX 0 Priority 500 AngleFromX 0 Priority 500 AngleFromX 0 Priority 500 AngleFromX 0 Priority 500 AngleFromX 0 Priority 500 AngleFromX 0 Priority 500 originOffsetX 0 originOffsetY 2300 envelopeLength 500 envelopeWidth 500 envelopeSpacing 0 grainDirection 0 objectSpacing 10 frameWidth 25 placementClearance 20
step "Arrange9" AngleFromX 0 Priority 500 AngleFromX 0 Priority 500 AngleFromX 0 Priority 500 AngleFromX 0 Priority 500 AngleFromX 0 Priority 500 AngleFromX 0 Priority 500 AngleFromX 0 Priority 500 originOffsetX 900 originOffsetY 0 envelopeLength 500 envelopeWidth 500 envelopeSpacing 0 grainDirection 0 objectSpacing 10 frameWidth 25 placementClearance 20
step "Arrange10" AngleFromX 0 Priority 500 AngleFromX 0 Priority 500 AngleFromX 0 Priority 500 AngleFromX 0 Priority 500 AngleFromX 0 Priority 500 AngleFromX 0 Priority 500 AngleFromX 0 Priority 500 originOffsetX 2300 originOffsetY 0 envelopeLength 500 envelopeWidth 500 envelopeSpacing 0 grainDirection 0 objectSpacing 10 frameWidth 25 placementClearance 20
sketch "Sketch42" plane through (0, 0, 0) normal (0, 0, 1) x axis (1, 0, 0)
